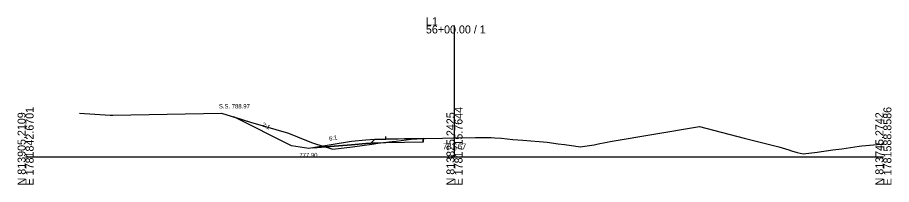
# Model space of a CAD drawing. Extents: x 5574 to 10203, y -10 to 9546.
# Drawn here: x 6597.2 to 6902.8, y 2990.3 to 3048.8 of the extents above; entities that cross this region are included whole.
import ezdxf

# ---------------------------------------------------------------- set-up
doc = ezdxf.new("R2010")
doc.units = 0
for name, color, linetype in [('Exist Cross Section Cell', 7, 'Continuous'), ('Exist XS Center Line Elevation Label', 7, 'Continuous'), ('Exist XS Ground Line', 7, 'Continuous'), ('Prop XS Ditch Slope Text', 7, 'Continuous'), ('Prop XS Ditch Standard Text', 7, 'Continuous'), ('Prop XS Dump Level', 7, 'Continuous'), ('Prop XS Earthwork Shape', 7, 'Continuous'), ('Prop XS EOT Tick Mark', 7, 'Continuous'), ('Prop XS Finish Grade', 7, 'Continuous'), ('Prop XS Finish Grade Earthwork', 7, 'Continuous'), ('Prop XS Finish Grade Paved Shoulder', 7, 'Continuous'), ('Prop XS Finish Grade Pavement', 7, 'Continuous'), ('Prop XS Hydro Typical Ditch Data', 7, 'Continuous'), ('Prop XS Pvmt Edge Slope', 7, 'Continuous'), ('Prop XS Side Slope Text', 7, 'Continuous'), ('Prop XS SS Elevation Text', 7, 'Continuous'), ('Prop XS Subgrade Earthwork', 7, 'Continuous'), ('Scratch_Level_3', 7, 'Continuous'), ('Scratch_Level_6', 7, 'Continuous')]:
    doc.layers.add(name, color=color, linetype=linetype)

msp = doc.modelspace()

# ---------------------------------------------------------------- linework, layer by layer
at = {"layer": 'Exist Cross Section Cell'}
for p, q in [((6750, 3000), (6750, 3046.02)), ((6600, 3000), (6750, 3000)), ((6750, 3000), (6900, 3000))]:
    msp.add_line(p, q, dxfattribs=at)
at = {"layer": 'Exist XS Ground Line'}
for p, q in [((6618.89, 3015.26), (6629.57, 3014.57)), ((6629.57, 3014.57), (6629.99, 3014.57)), ((6629.99, 3014.57), (6630.46, 3014.58)), ((6630.46, 3014.58), (6668.48, 3015.34)), ((6668.48, 3015.34), (6678.62, 3012.18)), ((6678.62, 3012.18), (6691.92, 3008.24)), ((6691.92, 3008.24), (6698.25, 3005.72)), ((6804.46, 3005.38), (6835.66, 3010.62)), ((6835.66, 3010.62), (6851.28, 3006.5)), ((6698.25, 3005.72), (6700.31, 3004.91)), ((6700.31, 3004.91), (6701.7, 3004.49)), ((6721.96, 3004.62), (6723.61, 3004.9)), ((6723.61, 3004.9), (6724.14, 3004.95)), ((6724.14, 3004.95), (6728.19, 3005.37)), ((6728.19, 3005.37), (6729.57, 3005.55)), ((6729.57, 3005.55), (6734.83, 3006.24)), ((6734.83, 3006.24), (6736.98, 3006.34)), ((6736.98, 3006.34), (6739.05, 3006.43)), ((6739.05, 3006.43), (6745.86, 3006.58)), ((6745.86, 3006.58), (6750, 3006.67)), ((6750, 3006.67), (6750.94, 3006.69)), ((6750.94, 3006.69), (6757.35, 3006.74)), ((6757.35, 3006.74), (6762.2, 3006.78)), ((6762.2, 3006.78), (6762.81, 3006.77)), ((6762.81, 3006.77), (6764.1, 3006.71)), ((6764.1, 3006.71), (6766.42, 3006.6)), ((6766.42, 3006.6), (6770.4, 3006.1)), ((6770.4, 3006.1), (6773.94, 3005.89)), ((6773.94, 3005.89), (6782.44, 3005.11)), ((6782.44, 3005.11), (6786.23, 3004.58)), ((6800.77, 3004.63), (6803.45, 3005.17)), ((6803.45, 3005.17), (6804.46, 3005.38)), ((6851.28, 3006.5), (6863.43, 3003.53)), ((6701.7, 3004.49), (6707.43, 3002.74)), ((6707.43, 3002.74), (6714.29, 3003.51)), ((6714.29, 3003.51), (6721.96, 3004.62)), ((6786.23, 3004.58), (6788.47, 3004.33)), ((6788.47, 3004.33), (6791.76, 3003.84)), ((6791.76, 3003.84), (6793.94, 3003.51)), ((6793.94, 3003.51), (6798.82, 3004.27)), ((6798.82, 3004.27), (6799.27, 3004.35)), ((6799.27, 3004.35), (6800.77, 3004.63)), ((6863.43, 3003.53), (6866.94, 3002.41)), ((6866.94, 3002.41), (6867.89, 3002.15)), ((6867.89, 3002.15), (6869.83, 3001.56)), ((6876.85, 3001.69), (6882.32, 3002.49)), ((6882.32, 3002.49), (6885.43, 3002.86)), ((6885.43, 3002.86), (6891.55, 3003.8)), ((6891.55, 3003.8), (6892.44, 3003.88)), ((6892.44, 3003.88), (6899.21, 3004.41)), ((6899.21, 3004.41), (6900, 3004.46)), ((6869.83, 3001.56), (6871.89, 3001.02)), ((6871.89, 3001.02), (6876.85, 3001.69))]:
    msp.add_line(p, q, dxfattribs=at)
at = {"layer": 'Prop XS Dump Level'}
msp.add_line((6739.05, 3006.45), (6726, 3006.19), dxfattribs=at)
msp.add_line((6739.05, 3006.45), (6726, 3006.19), dxfattribs=at)
at = {"layer": 'Prop XS Earthwork Shape'}
for points in [[(6701.7, 3004.49), (6704.93, 3003.5), (6700.43, 3003.14), (6699, 3002.9), (6693, 3003.9), (6672.86, 3013.97), (6678.62, 3012.18), (6691.92, 3008.24), (6698.25, 3005.72), (6700.31, 3004.91)], [(6726, 3004.88), (6723.16, 3004.82), (6723.61, 3004.9), (6724.14, 3004.95), (6728.19, 3005.37), (6729.57, 3005.55), (6734.83, 3006.24), (6736.98, 3006.34), (6739.05, 3006.43), (6739.05, 3005.18)], [(6714, 3004.23), (6704.93, 3003.5), (6707.43, 3002.74), (6714.29, 3003.51), (6721.96, 3004.62), (6723.16, 3004.82), (6722, 3004.79), (6720.72, 3004.76), (6719, 3004.63)]]:
    msp.add_lwpolyline(points, close=True, dxfattribs=at)
at = {"layer": 'Prop XS EOT Tick Mark'}
msp.add_line((6726, 3006.13), (6726, 3007.13), dxfattribs=at)
at = {"layer": 'Prop XS Finish Grade'}
for p, q in [((6714, 3005.4), (6700.43, 3003.14)), ((6719, 3005.8), (6714, 3005.4)), ((6722, 3006.04), (6719, 3005.8))]:
    msp.add_line(p, q, dxfattribs=at)
at = {"layer": 'Prop XS Finish Grade Earthwork'}
for p, q in [((6693, 3003.9), (6672.86, 3013.97)), ((6699, 3002.9), (6693, 3003.9)), ((6700.43, 3003.14), (6699, 3002.9))]:
    msp.add_line(p, q, dxfattribs=at)
at = {"layer": 'Prop XS Finish Grade Paved Shoulder'}
msp.add_line((6726, 3006.13), (6722, 3006.04), dxfattribs=at)
at = {"layer": 'Prop XS Finish Grade Pavement'}
msp.add_line((6739.05, 3006.43), (6726, 3006.13), dxfattribs=at)
at = {"layer": 'Prop XS Hydro Typical Ditch Data'}
for p, q in [((6693, 3003.9), (6672.86, 3013.97)), ((6714, 3005.4), (6699, 3002.9)), ((6699, 3002.9), (6693, 3003.9))]:
    msp.add_line(p, q, dxfattribs=at)
at = {"layer": 'Prop XS Pvmt Edge Slope'}
msp.add_line((6722, 3006.04), (6720.72, 3004.76), dxfattribs=at)
at = {"layer": 'Prop XS Subgrade Earthwork'}
for p, q in [((6726, 3004.88), (6722, 3004.79)), ((6739.05, 3005.18), (6726, 3004.88)), ((6739.05, 3005.18), (6739.05, 3006.43)), ((6714, 3004.23), (6700.43, 3003.14)), ((6719, 3004.63), (6714, 3004.23)), ((6720.72, 3004.76), (6719, 3004.63)), ((6722, 3004.79), (6720.72, 3004.76))]:
    msp.add_line(p, q, dxfattribs=at)
at = {"layer": 'Scratch_Level_3'}
for p, q in [((6714, 3005.4), (6700.43, 3003.14)), ((6719, 3005.8), (6714, 3005.4)), ((6722, 3006.04), (6719, 3005.8)), ((6720.72, 3004.76), (6722, 3006.04)), ((6700.43, 3003.14), (6714, 3004.23)), ((6714, 3004.23), (6719, 3004.63)), ((6719, 3004.63), (6720.72, 3004.76))]:
    msp.add_line(p, q, dxfattribs=at)
at = {"layer": 'Scratch_Level_6'}
for points in [[(6723.61, 3004.9), (6724.14, 3004.95), (6728.19, 3005.37), (6729.57, 3005.55), (6734.83, 3006.24), (6736.98, 3006.34), (6739.05, 3006.43), (6739.05, 3005.18), (6726, 3004.88), (6723.16, 3004.82)], [(6704.1, 3003.75), (6704.93, 3003.5), (6700.43, 3003.14)]]:
    msp.add_lwpolyline(points, close=True, dxfattribs=at)

# ---------------------------------------------------------------- texts
at = {"layer": 'Exist Cross Section Cell'}
for s, p in [('L1', (6740, 3046.02)), ('56+00.00 / 1', (6740, 3043.22))]:
    msp.add_text(s, height=2.8, dxfattribs=at).set_placement(p)
for s, p in [('E 1781842.6701', (6602.8, 2990)), ('E 1781715.7644', (6752.8, 2990)), ('E 1781588.8586', (6902.8, 2990)), ('N 813905.2109', (6600, 2990)), ('N 813825.2425', (6750, 2990)), ('N 813745.2742', (6900, 2990))]:
    msp.add_text(s, height=2.8, rotation=90, dxfattribs=at).set_placement(p)
at = {"layer": 'Exist XS Center Line Elevation Label'}
msp.add_text('781.67', height=2, dxfattribs=at).set_placement((6745.94, 3002.67))
at = {"layer": 'Prop XS Ditch Slope Text'}
msp.add_text('6:1', height=1.5, rotation=9.4623, dxfattribs=at).set_placement((6706.25, 3005.63))
at = {"layer": 'Prop XS Ditch Standard Text'}
msp.add_text('777.90', height=1.5, dxfattribs=at).set_placement((6695.74, 2999.9))
at = {"layer": 'Prop XS Dump Level'}
for s, height, p in [('Case4', 0.04, (6714, 3005.36)), ('Eop', 0.3, (6739.05, 3006.13))]:
    msp.add_text(s, height=height, dxfattribs=at).set_placement(p)
at = {"layer": 'Prop XS Side Slope Text'}
msp.add_text('2:1', height=1.5, rotation=333.4349, dxfattribs=at).set_placement((6682.52, 3010.82))
at = {"layer": 'Prop XS SS Elevation Text'}
msp.add_text('S.S. 788.97', height=1.5, dxfattribs=at).set_placement((6667.6, 3016.97))

doc.saveas('drawing.dxf')
